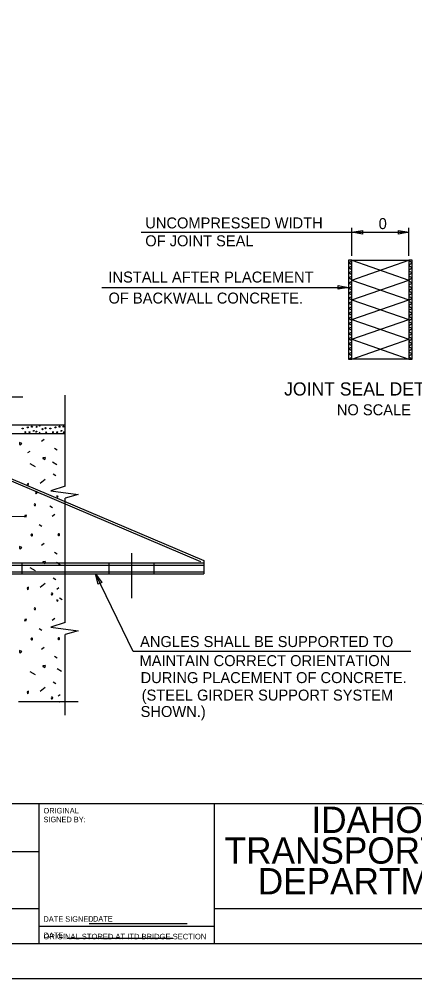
# Model space of a CAD drawing. Extents: x 0 to 11.3, y 0 to 7.9.
# Drawn here: x 3.739 to 5.619, y 0 to 4.557 of the extents above; entities that cross this region are included whole.
import ezdxf

# ---------------------------------------------------------------- set-up
doc = ezdxf.new("R2010")
doc.units = 0
for name, color, linetype in [('BORDER_ANNO_Cutsheet', 7, 'Continuous'), ('BRDG_ANNO_Anno-Large-Print', 7, 'Continuous'), ('BRDG_ANNO_Anno-Sheet', 7, 'Continuous'), ('BRDG_ANNO_Anno-Small-Print', 7, 'Continuous'), ('BRDG_ANNO_General-Notes', 7, 'Continuous'), ('BRDG_BASE_Dtlctrln', 7, 'Continuous'), ('BRDG_BASE_Hidden-Line', 7, 'Continuous'), ('BRDG_BASE_Obj-Line', 7, 'Continuous'), ('BRDG_BASE_Pattern', 7, 'Continuous')]:
    doc.layers.add(name, color=color, linetype=linetype)

msp = doc.modelspace()

# ---------------------------------------------------------------- linework, layer by layer
at = {"layer": 'BORDER_ANNO_Cutsheet'}
msp.add_lwpolyline([(0, 7.3333), (11.3333, 7.3333), (11.3333, 0), (0, 0)], close=True, dxfattribs=at)
at = {"layer": 'BRDG_ANNO_Anno-Large-Print'}
msp.add_line((3.9665, 0.1935), (4.4685, 0.1935), dxfattribs=at)
at = {"layer": 'BRDG_ANNO_Anno-Sheet'}
for p, q in [((0.5, 0.8333), (6.4167, 0.8333)), ((3.8333, 0.1667), (3.8333, 0.8333)), ((4.6667, 0.1667), (4.6667, 0.8333)), ((3.1667, 0.6042), (3.8333, 0.6042)), ((3.1667, 0.3333), (3.8333, 0.3333)), ((4.6667, 0.3333), (6.4167, 0.3333))]:
    msp.add_line(p, q, dxfattribs=at)
msp.add_lwpolyline([(0.5, 7.1667), (11.1667, 7.1667), (11.1667, 0.1667), (0.5, 0.1667)], close=True, dxfattribs=at)
at = {"layer": 'BRDG_ANNO_Anno-Small-Print'}
for p, q in [((3.8333, 0.25), (4.6667, 0.25)), ((4.0721, 0.2621), (4.5379, 0.2621))]:
    msp.add_line(p, q, dxfattribs=at)
at = {"layer": 'BRDG_ANNO_General-Notes'}
for p, q in [((5.3204, 3.433), (5.3204, 3.5668)), ((5.5912, 3.433), (5.5912, 3.5668)), ((4.3193, 3.5453), (5.3204, 3.5453)), ((5.3204, 3.5453), (5.3704, 3.5536)), ((5.3204, 3.5453), (5.5912, 3.5453)), ((5.3704, 3.537), (5.3204, 3.5453)), ((5.3704, 3.5536), (5.3704, 3.537)), ((5.5412, 3.537), (5.5412, 3.5536)), ((5.5412, 3.5536), (5.5912, 3.5453)), ((5.5912, 3.5453), (5.5412, 3.537)), ((4.1313, 3.2835), (5.3047, 3.2835)), ((5.2547, 3.2752), (5.2547, 3.2919)), ((5.2547, 3.2919), (5.3047, 3.2835)), ((5.3047, 3.2835), (5.2547, 3.2752)), ((3.7564, 2.7631), (3.2173, 2.7631)), ((4.2806, 1.5552), (4.1007, 1.9231)), ((4.1142, 1.8741), (4.1007, 1.9231)), ((4.1007, 1.9231), (4.131, 1.8823)), ((4.131, 1.8823), (4.1142, 1.8741)), ((5.5999, 1.5552), (4.2806, 1.5552))]:
    msp.add_line(p, q, dxfattribs=at)
at = {"layer": 'BRDG_BASE_Dtlctrln'}
for p, q in [((2.9021, 2.1974), (3.7739, 2.1963)), ((4.2728, 2.022), (4.2726, 1.8083))]:
    msp.add_line(p, q, dxfattribs=at)
at = {"layer": 'BRDG_BASE_Hidden-Line'}
for p, q in [((3.2821, 2.542), (4.6009, 1.9822)), ((3.2861, 2.5516), (4.6168, 1.9868)), ((3.3156, 1.9752), (4.6168, 1.9752)), ((3.3161, 1.9648), (4.6174, 1.9648)), ((3.7514, 1.9735), (3.7514, 1.9214)), ((4.1643, 1.9735), (4.1643, 1.9214)), ((4.3793, 1.9735), (4.3793, 1.9214)), ((4.6168, 1.9868), (4.6168, 1.9231)), ((3.3156, 1.9231), (4.6168, 1.9231)), ((3.3161, 1.9335), (4.6168, 1.9335))]:
    msp.add_line(p, q, dxfattribs=at)
at = {"layer": 'BRDG_BASE_Obj-Line'}
for p, q in [((3.958, 2.3396), (3.958, 2.7711)), ((3.3648, 2.6315), (3.958, 2.6315)), ((3.2901, 2.5903), (3.958, 2.5903)), ((3.958, 2.3396), (3.8897, 2.3174)), ((3.8897, 2.3174), (4.0192, 2.3003)), ((4.0192, 2.3003), (3.958, 2.2829)), ((3.958, 1.692), (3.958, 2.2829)), ((3.958, 1.692), (3.8897, 1.6698)), ((3.8897, 1.6698), (4.0192, 1.6528)), ((4.0192, 1.6528), (3.958, 1.6353)), ((3.958, 1.2523), (3.958, 1.6353)), ((4.0197, 1.3157), (3.7361, 1.3157))]:
    msp.add_line(p, q, dxfattribs=at)
for points in [[(5.3204, 3.4122), (5.3047, 3.4122), (5.3047, 2.9434), (5.3204, 2.9434)], [(5.3204, 3.4122), (5.5912, 3.4122), (5.5912, 2.9434), (5.3204, 2.9434)], [(5.6068, 3.4122), (5.5912, 3.4122), (5.5912, 2.9434), (5.6068, 2.9434)]]:
    msp.add_lwpolyline(points, close=True, dxfattribs=at)
at = {"layer": 'BRDG_BASE_Pattern'}
for p, q in [((5.3047, 3.4005), (5.3204, 3.4095)), ((5.3204, 3.3915), (5.3047, 3.4005)), ((5.3047, 3.3765), (5.3204, 3.3855)), ((5.3204, 3.3674), (5.3047, 3.3765)), ((5.3204, 3.4122), (5.5912, 3.3184)), ((5.3204, 3.3184), (5.5912, 3.4122)), ((5.6068, 3.4005), (5.5912, 3.4095)), ((5.5912, 3.3915), (5.6068, 3.4005)), ((5.6068, 3.3765), (5.5912, 3.3855)), ((5.5912, 3.3674), (5.6068, 3.3765)), ((5.3047, 3.3524), (5.3204, 3.3614)), ((5.3204, 3.3434), (5.3047, 3.3524)), ((5.3047, 3.3283), (5.3204, 3.3373)), ((5.3204, 3.3193), (5.3047, 3.3283)), ((5.6068, 3.3524), (5.5912, 3.3614)), ((5.5912, 3.3434), (5.6068, 3.3524)), ((5.6068, 3.3283), (5.5912, 3.3373)), ((5.5912, 3.3193), (5.6068, 3.3283)), ((5.3047, 3.3043), (5.3204, 3.3133)), ((5.3204, 3.2953), (5.3047, 3.3043)), ((5.3047, 3.2802), (5.3204, 3.2893)), ((5.3204, 3.2247), (5.5912, 3.3184)), ((5.3204, 3.3184), (5.5912, 3.2247)), ((5.6068, 3.3043), (5.5912, 3.3133)), ((5.5912, 3.2953), (5.6068, 3.3043)), ((5.6068, 3.2802), (5.5912, 3.2893)), ((5.3204, 3.2712), (5.3047, 3.2802)), ((5.3047, 3.2561), (5.3204, 3.2652)), ((5.3204, 3.2471), (5.3047, 3.2561)), ((5.3047, 3.2321), (5.3204, 3.2411)), ((5.5912, 3.2712), (5.6068, 3.2802)), ((5.6068, 3.2561), (5.5912, 3.2652)), ((5.5912, 3.2471), (5.6068, 3.2561)), ((5.6068, 3.2321), (5.5912, 3.2411)), ((5.3204, 3.2231), (5.3047, 3.2321)), ((5.3047, 3.2081), (5.3204, 3.2171)), ((5.3204, 3.199), (5.3047, 3.2081)), ((5.3047, 3.184), (5.3204, 3.193)), ((5.3204, 3.2247), (5.5912, 3.1309)), ((5.3204, 3.1309), (5.5912, 3.2247)), ((5.5912, 3.2231), (5.6068, 3.2321)), ((5.6068, 3.2081), (5.5912, 3.2171)), ((5.5912, 3.199), (5.6068, 3.2081)), ((5.6068, 3.184), (5.5912, 3.193)), ((5.3204, 3.175), (5.3047, 3.184)), ((5.3047, 3.1599), (5.3204, 3.169)), ((5.3204, 3.1509), (5.3047, 3.1599)), ((5.3047, 3.1359), (5.3204, 3.1449)), ((5.5912, 3.175), (5.6068, 3.184)), ((5.6068, 3.1599), (5.5912, 3.169)), ((5.5912, 3.1509), (5.6068, 3.1599)), ((5.6068, 3.1359), (5.5912, 3.1449)), ((5.3204, 3.1269), (5.3047, 3.1359)), ((5.3047, 3.1118), (5.3204, 3.1208)), ((5.3204, 3.1028), (5.3047, 3.1118)), ((5.3204, 3.0372), (5.5912, 3.1309)), ((5.3204, 3.1309), (5.5912, 3.0372)), ((5.5912, 3.1269), (5.6068, 3.1359)), ((5.6068, 3.1118), (5.5912, 3.1208)), ((5.5912, 3.1028), (5.6068, 3.1118)), ((5.3047, 3.0878), (5.3204, 3.0968)), ((5.3204, 3.0787), (5.3047, 3.0878)), ((5.3047, 3.0637), (5.3204, 3.0728)), ((5.3204, 3.0547), (5.3047, 3.0637)), ((5.6068, 3.0878), (5.5912, 3.0968)), ((5.5912, 3.0787), (5.6068, 3.0878)), ((5.6068, 3.0637), (5.5912, 3.0728)), ((5.5912, 3.0547), (5.6068, 3.0637)), ((5.3047, 3.0397), (5.3204, 3.0487)), ((5.3204, 3.0306), (5.3047, 3.0397)), ((5.3047, 3.0156), (5.3204, 3.0246)), ((5.3204, 3.0066), (5.3047, 3.0156)), ((5.3204, 3.0372), (5.5912, 2.9434)), ((5.3204, 2.9434), (5.5912, 3.0372)), ((5.6068, 3.0397), (5.5912, 3.0487)), ((5.5912, 3.0306), (5.6068, 3.0397)), ((5.6068, 3.0156), (5.5912, 3.0246)), ((5.5912, 3.0066), (5.6068, 3.0156)), ((5.3047, 2.9916), (5.3204, 3.0006)), ((5.3204, 2.9826), (5.3047, 2.9916)), ((5.3047, 2.9675), (5.3204, 2.9765)), ((5.3204, 2.9585), (5.3047, 2.9675)), ((5.6068, 2.9916), (5.5912, 3.0006)), ((5.5912, 2.9826), (5.6068, 2.9916)), ((5.6068, 2.9675), (5.5912, 2.9765)), ((5.5912, 2.9585), (5.6068, 2.9675)), ((5.3047, 2.9434), (5.3204, 2.9524)), ((5.6068, 2.9434), (5.5912, 2.9524)), ((3.8576, 2.5606), (3.8455, 2.5515)), ((3.9071, 2.5196), (3.9195, 2.5118)), ((3.7885, 2.5049), (3.7786, 2.4974)), ((3.7893, 2.448), (3.814, 2.4323)), ((3.8969, 2.4551), (3.9173, 2.4423)), ((3.8622, 2.3712), (3.8382, 2.353)), ((3.9002, 2.3979), (3.9126, 2.3901)), ((3.8843, 2.2459), (3.8967, 2.2381)), ((3.9083, 2.2047), (3.8962, 2.1956)), ((3.8341, 2.1582), (3.8464, 2.1504)), ((3.8576, 2.0667), (3.8455, 2.0576)), ((3.9071, 2.0257), (3.9195, 2.0179)), ((3.9163, 1.9783), (3.9335, 1.9675)), ((3.7893, 1.9541), (3.814, 1.9384)), ((3.8622, 1.8773), (3.8382, 1.8591)), ((3.9002, 1.904), (3.9126, 1.8961)), ((3.9272, 1.8569), (3.9176, 1.8496)), ((3.9301, 1.8096), (3.9425, 1.8018)), ((3.9083, 1.7108), (3.8962, 1.7017)), ((3.8341, 1.6643), (3.8464, 1.6565)), ((3.8576, 1.5728), (3.8455, 1.5636)), ((3.9071, 1.5318), (3.9195, 1.524)), ((3.7893, 1.4602), (3.814, 1.4446)), ((3.9199, 1.4737), (3.9391, 1.4618)), ((3.8622, 1.3835), (3.8382, 1.3652)), ((3.9002, 1.4101), (3.9126, 1.4023)), ((3.9333, 1.3492), (3.9239, 1.3421)), ((3.9301, 1.3157), (3.9315, 1.3148))]:
    msp.add_line(p, q, dxfattribs=at)
for points in [[(3.7401, 2.5475), (3.7396, 2.5376), (3.7456, 2.5362), (3.7514, 2.5429)], [(3.8565, 2.4746), (3.851, 2.4741), (3.851, 2.4714), (3.857, 2.4672), (3.8602, 2.4667), (3.8634, 2.4755)], [(3.7768, 2.3495), (3.7796, 2.3411), (3.7796, 2.342), (3.7833, 2.3513), (3.7823, 2.3531)], [(3.8165, 2.3099), (3.8179, 2.3054), (3.8192, 2.3054), (3.8211, 2.3058), (3.8224, 2.3071), (3.8238, 2.3099), (3.8234, 2.3127), (3.8211, 2.3132), (3.8201, 2.3141), (3.8183, 2.3141)], [(3.9181, 2.2936), (3.9179, 2.2886), (3.9208, 2.288), (3.9237, 2.2913)], [(3.8118, 2.2558), (3.8095, 2.2507), (3.8122, 2.2479), (3.8155, 2.2479), (3.8168, 2.2494), (3.8168, 2.2521), (3.8164, 2.2534), (3.8149, 2.2549)], [(3.7649, 2.1997), (3.764, 2.1942), (3.7704, 2.1952), (3.7723, 2.196), (3.7732, 2.2016)], [(3.797, 2.1124), (3.7947, 2.1073), (3.7974, 2.1045), (3.8007, 2.1045), (3.8021, 2.106), (3.8021, 2.1087), (3.8016, 2.1101), (3.8002, 2.1115)], [(3.9251, 2.114), (3.9228, 2.109), (3.9255, 2.1061), (3.9287, 2.1061), (3.9301, 2.1076), (3.9301, 2.1103), (3.9296, 2.1116), (3.9282, 2.1131)], [(3.7401, 2.0536), (3.7396, 2.0437), (3.7456, 2.0423), (3.7514, 2.049)], [(3.8565, 1.9807), (3.851, 1.9802), (3.851, 1.9774), (3.857, 1.9733), (3.8602, 1.9729), (3.8634, 1.9816)], [(3.7768, 1.8556), (3.7796, 1.8472), (3.7796, 1.8482), (3.7833, 1.8574), (3.7823, 1.8592)], [(3.891, 1.8278), (3.8925, 1.8232), (3.8938, 1.8232), (3.8957, 1.8236), (3.897, 1.8249), (3.8984, 1.8278), (3.898, 1.8305), (3.8957, 1.831), (3.8947, 1.8319), (3.8929, 1.8319)], [(3.9181, 1.7997), (3.9179, 1.7948), (3.9208, 1.7941), (3.9237, 1.7974)], [(3.8118, 1.7619), (3.8095, 1.7568), (3.8122, 1.754), (3.8155, 1.754), (3.8168, 1.7555), (3.8168, 1.7582), (3.8164, 1.7595), (3.8149, 1.761)], [(3.7649, 1.7058), (3.764, 1.7003), (3.7704, 1.7012), (3.7723, 1.7021), (3.7732, 1.7077)], [(3.797, 1.6185), (3.7947, 1.6134), (3.7974, 1.6106), (3.8007, 1.6106), (3.8021, 1.6121), (3.8021, 1.6148), (3.8016, 1.6161), (3.8002, 1.6176)], [(3.9251, 1.6201), (3.9228, 1.6151), (3.9255, 1.6122), (3.9287, 1.6122), (3.9301, 1.6137), (3.9301, 1.6164), (3.9296, 1.6177), (3.9282, 1.6192)], [(3.7401, 1.5597), (3.7396, 1.5498), (3.7456, 1.5484), (3.7514, 1.5551)], [(3.8565, 1.4868), (3.851, 1.4863), (3.851, 1.4835), (3.857, 1.4794), (3.8602, 1.479), (3.8634, 1.4877)], [(3.7768, 1.3617), (3.7796, 1.3534), (3.7796, 1.3543), (3.7833, 1.3635), (3.7823, 1.3654)], [(3.891, 1.3339), (3.8925, 1.3293), (3.8938, 1.3293), (3.8957, 1.3297), (3.897, 1.3311), (3.8984, 1.3339), (3.898, 1.3366), (3.8957, 1.3371), (3.8947, 1.3381), (3.8929, 1.3381)]]:
    msp.add_lwpolyline(points, close=True, dxfattribs=at)
for centre in [(3.7793, 2.619), (3.7876, 2.5958), (3.799, 2.6222), (3.8491, 2.6104), (3.9111, 2.619), (3.9194, 2.5958), (3.9308, 2.6222)]:
    msp.add_circle(centre, 0.00244, dxfattribs=at)
for centre, major_axis in [((3.7552, 2.6135), (0.00275, 0)), ((3.7675, 2.5958), (0, -0.00275)), ((3.8074, 2.6023), (-0.00195, -0.00195)), ((3.8203, 2.5986), (-0.00195, -0.00195)), ((3.8213, 2.6215), (0, -0.00275)), ((3.8362, 2.627), (0, -0.00275)), ((3.8636, 2.6154), (0, -0.00275)), ((3.887, 2.6135), (0.00275, 0)), ((3.8993, 2.5958), (0, -0.00275)), ((3.9392, 2.6023), (-0.00195, -0.00195)), ((3.9488, 2.6223), (0, -0.00275)), ((3.9502, 2.5958), (-0.00195, -0.00195)), ((3.8666, 2.5957), (0.00275, 0))]:
    msp.add_ellipse(centre, major_axis=major_axis, ratio=0.5, dxfattribs=at)
msp.add_ellipse((3.8354, 2.593), major_axis=(0, -0.00275), ratio=0.5, start_param=0.00615, end_param=6.277035, dxfattribs=at)

# ---------------------------------------------------------------- texts
at = {"layer": 'BRDG_ANNO_Anno-Large-Print'}
msp.add_text('DATE:', height=0.02624, dxfattribs=at).set_placement((3.855, 0.1935))
at = {"layer": 'BRDG_ANNO_Anno-Sheet'}
for s, p in [('IDAHO', (5.1279, 0.6927)), ('TRANSPORTATION', (4.7156, 0.5469)), ('DEPARTMENT', (4.8731, 0.401))]:
    msp.add_text(s, height=0.125, dxfattribs=at).set_placement(p)
at = {"layer": 'BRDG_ANNO_Anno-Small-Print'}
for s, height, p in [('ORIGINAL', 0.02625, (3.8542, 0.7854)), ('SIGNED BY:', 0.02625, (3.8542, 0.7435)), ('DATE SIGNED:', 0.02625, (3.8542, 0.2708)), ('DATE', 0.02624, (4.0896, 0.2719)), ('ORIGINAL STORED AT ITD BRIDGE SECTION', 0.026072, (3.8542, 0.1876))]:
    msp.add_text(s, height=height, dxfattribs=at).set_placement(p)
at = {"layer": 'BRDG_ANNO_General-Notes'}
for s, height, p in [('UNCOMPRESSED WIDTH', 0.052083, (4.338, 3.5638)), ('0', 0.0521, (5.4475, 3.5606)), ('OF JOINT SEAL', 0.052083, (4.338, 3.4789)), ('INSTALL AFTER PLACEMENT', 0.052083, (4.1628, 3.3068)), ('OF BACKWALL CONCRETE.', 0.052083, (4.1633, 3.2069)), ('JOINT SEAL DETAIL', 0.0625, (4.9981, 2.7701)), ('NO SCALE', 0.05208, (5.2488, 2.6764)), ('ANGLES SHALL BE SUPPORTED TO', 0.052083, (4.3134, 1.5756)), ('MAINTAIN CORRECT ORIENTATION', 0.052083, (4.3108, 1.4849)), ('DURING PLACEMENT OF CONCRETE.', 0.052083, (4.3159, 1.4044)), ('(STEEL GIRDER SUPPORT SYSTEM', 0.052083, (4.3209, 1.3214)), ('SHOWN.)', 0.05208, (4.3159, 1.2433))]:
    msp.add_text(s, height=height, dxfattribs=at).set_placement(p)

doc.saveas('drawing.dxf')
